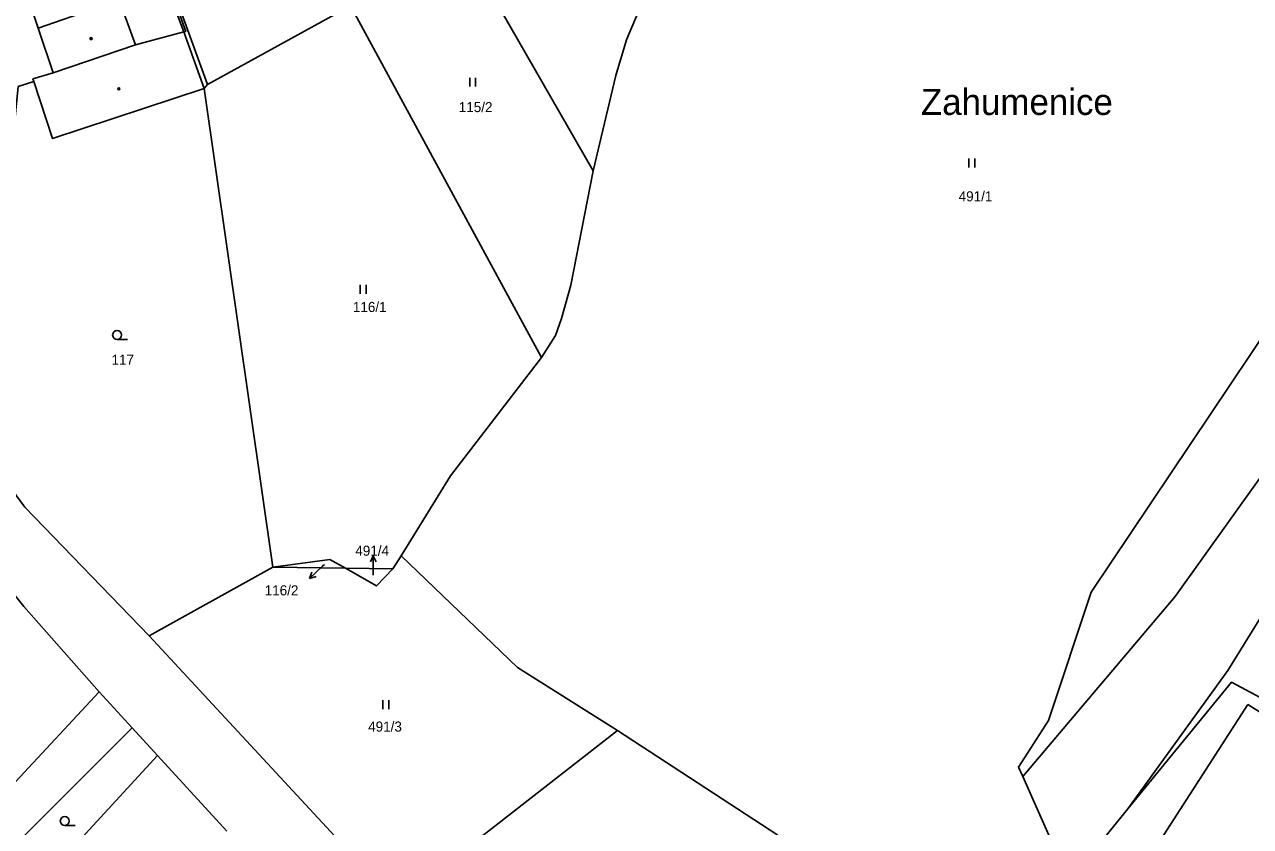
# Model space of a CAD drawing. Extents: x -757266 to -753360, y -1162585 to -1157740.
# Drawn here: x -754934.7 to -754727.9, y -1161700.2 to -1161564.9 of the extents above; entities that cross this region are included whole.
import ezdxf

# ---------------------------------------------------------------- set-up
doc = ezdxf.new("R2010")
doc.units = 0
for name, color, linetype in [('Hranice parcel', 7, 'Continuous'), ('Parcelní čísla', 7, 'Continuous'), ('Pop  PČ popisy', 7, 'Continuous'), ('Vnitřní kresba', 7, 'Continuous'), ('Značky budov', 7, 'Continuous'), ('Značky kultur', 7, 'Continuous')]:
    doc.layers.add(name, color=color, linetype=linetype)

msp = doc.modelspace()

# ---------------------------------------------------------------- linework, layer by layer
at = {"layer": 'Hranice parcel'}
for p, q in [((-754868.43, -1161538), (-754838.77, -1161589.54)), ((-754879.75, -1161561.7), (-754847.48, -1161621.03)), ((-754892.83, -1161656.43), (-754904.45, -1161575.69)), ((-754872.57, -1161656.7), (-754871.2, -1161654.49)), ((-754913.71, -1161667.99), (-754892.83, -1161656.43)), ((-754892.83, -1161656.43), (-754880.6, -1161656.59)), ((-754880.6, -1161656.59), (-754872.57, -1161656.7)), ((-754871.95, -1161713.02), (-754913.71, -1161667.99)), ((-754916.55, -1161683.55), (-754922.12, -1161677.47)), ((-754912.31, -1161688.18), (-754916.55, -1161683.55)), ((-754871.95, -1161713.02), (-754834.66, -1161683.96)), ((-754834.66, -1161683.96), (-754807.62, -1161701.64)), ((-754948.77, -1161727.83), (-754912.31, -1161688.18)), ((-754900.61, -1161700.97), (-754912.31, -1161688.18)), ((-754761.02, -1161703.65), (-754766.3, -1161691.75)), ((-754748.55, -1161697.18), (-754758.49, -1161709.34))]:
    msp.add_line(p, q, dxfattribs=at)
for points in [[(-754766.3, -1161691.75), (-754767.01, -1161690.15), (-754761.96, -1161682.3), (-754754.74, -1161660.64), (-754700.98, -1161580.45), (-754621.51, -1161435.14)], [(-754766.3, -1161691.75), (-754740.57, -1161661.36), (-754707.05, -1161614.54), (-754689.12, -1161585.41), (-754655.31, -1161521.67), (-754647.89, -1161505.85), (-754628.11, -1161471.88), (-754612.63, -1161441.92)], [(-754748.55, -1161697.18), (-754731.71, -1161673.87), (-754721.26, -1161657.03), (-754686.67, -1161603.4), (-754653.13, -1161544.11), (-754633.11, -1161503.51), (-754603.21, -1161449.04)], [(-754925.06, -1161525.14), (-754911.19, -1161554.45), (-754911.64, -1161554.65), (-754907.52, -1161566.03), (-754907.88, -1161566.11), (-754904.45, -1161575.69)], [(-754838.77, -1161589.54), (-754834.97, -1161573.46), (-754833.15, -1161567.45), (-754829.7, -1161559.15)], [(-754904.45, -1161575.69), (-754903.85, -1161574.99), (-754880.14, -1161561.96), (-754879.75, -1161561.7)], [(-754935.78, -1161575.33), (-754936.51, -1161582.74), (-754937.52, -1161592.92), (-754942.18, -1161617.94), (-754943.06, -1161625.93), (-754942.03, -1161633.15), (-754939.91, -1161639.29), (-754934.67, -1161646.27), (-754913.71, -1161667.99)], [(-754904.45, -1161575.69), (-754929.99, -1161584.11), (-754933.16, -1161574.51), (-754935.78, -1161575.33)], [(-754847.48, -1161621.03), (-754845.13, -1161617.34), (-754844.11, -1161614.49), (-754842.57, -1161608.83), (-754838.77, -1161589.54)], [(-754847.48, -1161621.03), (-754862.84, -1161641.01), (-754871.2, -1161654.49)], [(-754922.12, -1161677.47), (-754934.85, -1161663.03), (-754943.9, -1161651.8), (-754948.65, -1161643.42)], [(-754871.2, -1161654.49), (-754851.55, -1161673.34), (-754834.66, -1161683.96)], [(-754892.83, -1161656.43), (-754883.2, -1161655.11), (-754880.6, -1161656.59)], [(-754872.57, -1161656.7), (-754875.36, -1161659.59), (-754880.6, -1161656.59)], [(-754714.14, -1161684.89), (-754731.08, -1161675.82), (-754748.55, -1161697.18)], [(-754942.13, -1161699.15), (-754936.26, -1161692.66), (-754922.12, -1161677.47)], [(-754952.34, -1161724.76), (-754945.68, -1161717.94), (-754941, -1161713.33), (-754936.08, -1161708.51), (-754934.57, -1161706.55), (-754937.36, -1161704.29), (-754937.15, -1161704.08), (-754916.55, -1161683.55)]]:
    msp.add_lwpolyline(points, dxfattribs=at)
at = {"layer": 'Pop  PČ popisy'}
for p, q in [((-754884.43, -1161656.27), (-754886.625, -1161658.317)), ((-754884.11, -1161655.96), (-754884.43, -1161656.27)), ((-754875.88, -1161654.529), (-754876.381, -1161655.53)), ((-754875.88, -1161657.53), (-754875.88, -1161654.529)), ((-754875.88, -1161654.529), (-754875.379, -1161655.53)), ((-754886.625, -1161658.317), (-754886.234, -1161657.267)), ((-754886.625, -1161658.317), (-754885.551, -1161658)), ((-754875.88, -1161657.75), (-754875.88, -1161657.53))]:
    msp.add_line(p, q, dxfattribs=at)
at = {"layer": 'Vnitřní kresba'}
for p, q in [((-754912.06, -1161554.86), (-754907.88, -1161566.11)), ((-754932.41, -1161565.5), (-754934.59, -1161558.84)), ((-754916.01, -1161568.32), (-754918.74, -1161560.68)), ((-754932.41, -1161565.5), (-754923.98, -1161562.54)), ((-754908.11, -1161563.22), (-754903.85, -1161574.99)), ((-754929.92, -1161573.03), (-754932.41, -1161565.5)), ((-754907.88, -1161566.11), (-754916.01, -1161568.32)), ((-754916.01, -1161568.32), (-754929.92, -1161573.03)), ((-754929.92, -1161573.03), (-754933.32, -1161574.04)), ((-754933.32, -1161574.04), (-754933.16, -1161574.51)), ((-754782.49, -1161763.64), (-754728.32, -1161679.57)), ((-754728.32, -1161679.57), (-754678.1, -1161711.64))]:
    msp.add_line(p, q, dxfattribs=at)
at = {"layer": 'Značky budov'}
for centre in [(-754923.5068, -1161567.2492), (-754918.8068, -1161575.7192)]:
    msp.add_circle(centre, 0.175, dxfattribs=at)
at = {"layer": 'Značky kultur'}
for p, q in [((-754859.621, -1161575.35), (-754859.621, -1161573.85)), ((-754858.62, -1161575.35), (-754858.62, -1161573.85)), ((-754775.411, -1161589), (-754775.411, -1161587.5)), ((-754774.41, -1161589), (-754774.41, -1161587.5)), ((-754878.111, -1161610.3), (-754878.111, -1161608.8)), ((-754877.11, -1161610.3), (-754877.11, -1161608.8)), ((-754919.113, -1161617.99), (-754917.363, -1161617.99)), ((-754874.291, -1161680.35), (-754874.291, -1161678.85)), ((-754873.29, -1161680.35), (-754873.29, -1161678.85)), ((-754927.943, -1161699.99), (-754926.193, -1161699.99))]:
    msp.add_line(p, q, dxfattribs=at)
for centre in [(-754919.1129, -1161617.2398), (-754927.9429, -1161699.2398)]:
    msp.add_circle(centre, 0.75, dxfattribs=at)

# ---------------------------------------------------------------- texts
at = {"layer": 'Parcelní čísla'}
for s, p in [('115/2', (-754861.46, -1161579.65)), ('491/1', (-754777.11, -1161594.7)), ('116/1', (-754879.33, -1161613.37)), ('117', (-754920.06, -1161622.28)), ('491/4', (-754878.92, -1161654.49)), ('116/2', (-754894.207, -1161661.178)), ('491/3', (-754876.75, -1161684.16))]:
    msp.add_text(s, height=1.7, dxfattribs=at).set_placement(p)
at = {"layer": 'Pop  PČ popisy'}
msp.add_text('Zahumenice', height=4.4, dxfattribs=at).set_placement((-754783.48, -1161580.13))

doc.saveas('drawing.dxf')
